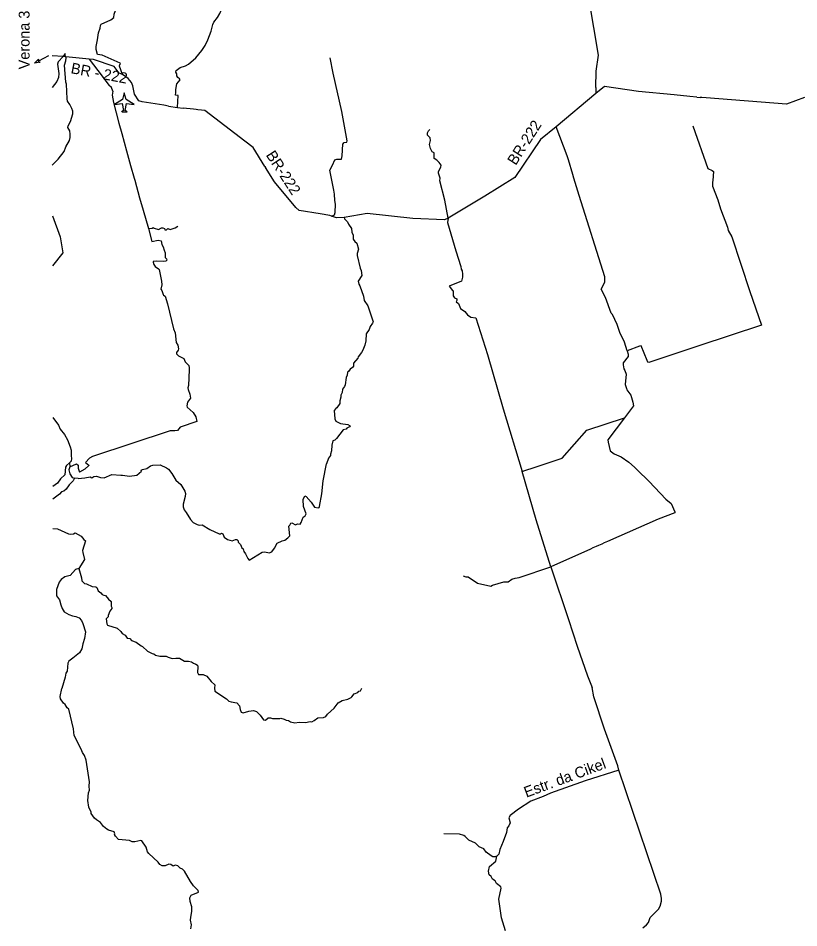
# Model space of a CAD drawing. Extents: x 332 to 501, y 9447 to 9559.
# Drawn here: x 332.35 to 359.78, y 9494.03 to 9526 of the extents above; entities that cross this region are included whole.
import ezdxf

# ---------------------------------------------------------------- set-up
doc = ezdxf.new("R2010")
doc.units = 0
for name, color, linetype in [('Level 1', 7, 'Continuous'), ('Level 12', 7, 'Continuous'), ('Level 2', 7, 'Continuous'), ('Level 31', 7, 'Continuous'), ('Level 4', 7, 'Continuous'), ('Level 5', 7, 'Continuous'), ('Level 6', 7, 'Continuous'), ('Level 8', 7, 'Continuous')]:
    doc.layers.add(name, color=color, linetype=linetype)

msp = doc.modelspace()

# ---------------------------------------------------------------- linework, layer by layer
at = {"layer": 'Level 1'}
for p, q in [((336.0741, 9523.3737), (336.0091, 9523.1363)), ((336.1441, 9523.1387), (336.0741, 9523.3737)), ((336.0091, 9523.1363), (335.7266, 9522.9563)), ((335.7266, 9522.9563), (336.0016, 9523.0013)), ((336.0016, 9523.0013), (336.0491, 9522.7487)), ((336.1066, 9522.7487), (336.1516, 9523.0013)), ((336.4266, 9522.9563), (336.1441, 9523.1387)), ((336.1516, 9523.0013), (336.4266, 9522.9563)), ((336.0491, 9522.7487), (335.9791, 9522.7037)), ((336.0016, 9522.7037), (336.1516, 9522.7037)), ((336.1741, 9522.7037), (336.1066, 9522.7487)), ((336.1516, 9522.7037), (336.1741, 9522.7037))]:
    msp.add_line(p, q, dxfattribs=at)
at = {"layer": 'Level 12'}
msp.add_line((333.4081, 9524.6683), (333.055, 9524.4804), dxfattribs=at)
msp.add_lwpolyline([(333.0652, 9524.5527), (333.0553, 9524.5395), (333.0502, 9524.5277), (333.0476, 9524.5093), (333.0517, 9524.4866), (333.055, 9524.4804), (333.0643, 9524.4672), (333.0753, 9524.4572), (333.0889, 9524.4509), (333.1041, 9524.4477), (333.1207, 9524.4485), (332.9217, 9524.4095)], close=True, dxfattribs=at)
at = {"layer": 'Level 2'}
for points in [[(333.9235, 9524.6472), (333.535, 9524.6698)], [(334.0181, 9524.6391), (333.9235, 9524.6472)], [(334.8453, 9524.5576), (334.0181, 9524.6391)], [(335.7215, 9524.2976), (334.991, 9524.5432), (334.8453, 9524.5576)], [(336.0143, 9524.0187), (335.897, 9524.066), (335.7215, 9524.2976)], [(337.4688, 9522.9428), (336.7, 9523.054), (336.587, 9523.092), (336.428, 9523.324), (336.37, 9523.616), (336.324, 9523.735), (336.207, 9523.873), (336.0143, 9524.0187)], [(355.3959, 9523.2977), (354.1443, 9523.4167), (352.9539, 9523.5929), (352.6494, 9523.3443)], [(352.6494, 9523.3443), (351.2461, 9522.1806)], [(355.9458, 9523.2454), (355.3959, 9523.2977)], [(356.1976, 9523.2249), (355.9458, 9523.2454)], [(337.631, 9522.9075), (337.4688, 9522.9428)], [(356.1976, 9523.2249), (356.3094, 9523.2108)], [(356.3767, 9523.2044), (356.3094, 9523.2108)], [(356.5186, 9523.1911), (356.3767, 9523.2044)], [(359.9733, 9523.2053), (359.3502, 9522.9681), (356.5186, 9523.1911)], [(337.631, 9522.9075), (337.939, 9522.8614)], [(337.939, 9522.8614), (338.1482, 9522.8301)], [(338.5034, 9522.795), (338.1482, 9522.8301)], [(338.6059, 9522.7819), (338.5034, 9522.795)], [(338.6545, 9522.7758), (338.6059, 9522.7819)], [(338.7834, 9522.7652), (338.6545, 9522.7758)], [(338.9037, 9522.7565), (338.7834, 9522.7652)], [(340.3057, 9521.6762), (338.9037, 9522.7565)], [(351.2461, 9522.1806), (350.7068, 9521.7347), (349.7974, 9520.4022), (348.7487, 9519.7374), (347.4519, 9518.9685)], [(341.0112, 9520.7828), (340.5986, 9521.4515), (340.3057, 9521.6762)], [(341.0112, 9520.7828), (341.0313, 9520.7476)], [(341.3576, 9520.2458), (341.0313, 9520.7476)], [(342.959, 9519.1147), (342.2235, 9519.2394), (342.1022, 9519.342), (341.3576, 9520.2458)], [(343.3553, 9519.0321), (343.302, 9519.0566), (342.959, 9519.1147)], [(347.4519, 9518.9685), (347.3239, 9518.9044), (346.2112, 9518.9605), (344.6068, 9519.1287), (343.805, 9518.995)], [(343.805, 9518.995), (343.5341, 9518.9845), (343.3553, 9519.0321)]]:
    msp.add_lwpolyline(points, dxfattribs=at)
at = {"layer": 'Level 4'}
for points in [[(339.2202, 9525.8532), (339.3509, 9526.0211), (339.4284, 9526.1549), (339.4636, 9526.2465), (339.4777, 9526.4155), (339.5693, 9526.648), (339.7876, 9527.0706), (339.999, 9527.4228), (340.0483, 9527.5848), (339.9708, 9528.5005), (340.2173, 9528.74), (340.2737, 9528.7612), (340.3165, 9528.8076)], [(352.6514, 9523.5639), (352.6517, 9524.1375), (352.7345, 9524.693), (352.2393, 9527.6988)], [(335.909, 9524.309), (335.913, 9524.367), (335.938, 9524.393), (335.929, 9524.417), (335.292, 9524.697), (335.13, 9524.716), (335.084, 9524.893), (335.083, 9524.998), (335.139, 9525.23), (335.167, 9525.477), (335.222, 9525.649), (335.233, 9525.738), (335.262, 9525.787), (335.6, 9525.941), (335.708, 9526.015), (335.724, 9526.14), (335.764, 9526.266), (336.093, 9526.829)], [(337.8911, 9523.4836), (337.917, 9523.685), (338.035, 9523.823), (338.017, 9523.869), (337.955, 9523.915), (337.922, 9523.969), (337.917, 9524.043), (337.881, 9524.094), (337.896, 9524.162), (338.039, 9524.261), (338.228, 9524.326), (338.334, 9524.38), (338.585, 9524.607), (338.801, 9524.856), (338.917, 9525.032), (339.014, 9525.229), (339.128, 9525.534), (339.186, 9525.777), (339.2202, 9525.8532)], [(336.0143, 9524.0187), (335.909, 9524.309)], [(352.6514, 9523.5639), (352.6494, 9523.3443)], [(337.8816, 9523.3829), (337.8851, 9523.4365)], [(337.8851, 9523.4365), (337.8911, 9523.4836)], [(347.4519, 9518.9685), (347.4283, 9518.8161), (347.7248, 9517.8154), (347.9027, 9517.2743), (347.9155, 9517.1802)], [(347.9155, 9517.1802), (347.9446, 9517.1219), (347.9636, 9517.0028)], [(347.9636, 9517.0028), (347.963, 9516.896), (347.9297, 9516.7564), (347.4941, 9516.5735), (347.6139, 9516.4274)], [(347.6139, 9516.4274), (347.6284, 9516.4108), (347.6284, 9516.2402), (347.6803, 9516.1734), (347.7619, 9516.1289), (347.7619, 9516.077), (347.7396, 9516.0251), (347.8212, 9515.9658), (347.8953, 9515.7952), (348.0435, 9515.6913), (348.1399, 9515.5726), (348.2585, 9515.4836), (348.429, 9515.4614), (348.8441, 9514.1729), (349.3927, 9512.2696), (350.0534, 9510.0646)], [(351.0641, 9506.7186), (350.5463, 9508.3639), (350.0534, 9510.0646)], [(351.0641, 9506.7186), (351.6898, 9504.8611), (351.9871, 9503.9312), (352.35, 9502.8786), (352.5189, 9502.4702)], [(353.453, 9499.569), (353.418, 9499.717), (352.949, 9501.009), (352.571, 9502.149), (352.5189, 9502.4702)], [(353.453, 9499.569), (352.272, 9499.196), (351.049, 9498.765), (350.8, 9498.641), (350.367, 9498.48), (349.928, 9498.197), (349.64, 9497.981), (349.592, 9497.889), (349.632, 9497.712), (349.585, 9497.609), (349.529, 9497.547), (349.503, 9497.383), (349.391, 9497.059), (349.272, 9496.786), (349.24, 9496.612), (349.163, 9496.549)]]:
    msp.add_lwpolyline(points, dxfattribs=at)
at = {"layer": 'Level 5'}
for points in [[(333.9235, 9524.6472), (333.7523, 9524.4593), (333.7328, 9524.3744), (333.7719, 9524.0548), (333.7654, 9523.9112), (333.7067, 9523.7742), (333.5372, 9523.5608)], [(333.5426, 9520.8298), (333.751, 9521.036), (333.967, 9521.311), (334.023, 9521.477), (334.154, 9521.697), (334.17, 9521.804), (334.178, 9521.921), (334.165, 9522.032), (334.085, 9522.152), (334.099, 9522.216), (334.18, 9522.37), (334.264, 9522.634), (334.261, 9522.724), (334.233, 9522.824), (334.165, 9522.967), (334.083, 9523.076), (334.065, 9523.166), (334.039, 9523.676), (334.019, 9523.742), (333.971, 9524.34), (334.016, 9524.495), (334.031, 9524.603), (334.0181, 9524.6391)], [(334.002, 9524.75), (333.9235, 9524.6472)], [(334.0181, 9524.6391), (334.001, 9524.687), (334.002, 9524.75)], [(334.8453, 9524.5576), (335.1499, 9524.1544)], [(343.4354, 9519.9492), (343.2997, 9520.6532), (343.3958, 9520.8307), (343.4698, 9521.0157), (343.5438, 9521.0379), (343.7066, 9521.0453), (343.7288, 9521.1637), (343.751, 9521.5706), (343.8028, 9521.6224), (343.8989, 9521.6372), (343.9063, 9521.6816), (343.714, 9522.7174), (343.4106, 9524.0636), (343.3066, 9524.6025)], [(335.1499, 9524.1544), (335.5455, 9523.6255)], [(335.6673, 9523.4364), (335.6199, 9523.5583), (335.5455, 9523.6255)], [(335.6673, 9523.4364), (335.648, 9523.288), (335.696, 9523.031), (335.885, 9522.301)], [(335.885, 9522.301), (335.9847, 9521.9435)], [(347.138, 9520.9247), (347.0586, 9521.0036), (346.9649, 9521.0661), (346.9649, 9521.2615), (346.8946, 9521.3006), (346.8399, 9521.41), (346.8009, 9521.5507), (346.8399, 9521.6914), (346.824, 9521.7937), (346.7333, 9521.8821), (346.7333, 9521.9657), (346.7595, 9522.0373), (346.8121, 9522.0874)], [(351.638, 9521.1598), (351.2461, 9522.1806)], [(356.0594, 9522.2118), (356.5866, 9520.7099), (356.7326, 9520.6481), (356.7775, 9520.6043), (356.7606, 9520.2898), (356.7438, 9520.228), (356.7494, 9520.0932), (356.9346, 9519.617), (357.0244, 9519.2912), (357.277, 9518.6471), (357.2995, 9518.5292), (357.4286, 9518.3101), (358.0531, 9516.3915)], [(335.9847, 9521.9435), (336.1568, 9521.3369)], [(336.1568, 9521.3369), (336.298, 9520.813)], [(351.6857, 9521.013), (351.638, 9521.1598)], [(351.8387, 9520.5037), (351.6857, 9521.013)], [(336.298, 9520.813), (336.418, 9520.371)], [(347.4519, 9518.9685), (347.335, 9519.5949), (347.1688, 9520.2782), (347.1749, 9520.3706), (347.1195, 9520.5491), (347.1134, 9520.6107), (347.1934, 9520.7646), (347.2057, 9520.8262), (347.138, 9520.9247)], [(336.418, 9520.371), (336.445, 9520.297)], [(351.8765, 9520.378), (351.8387, 9520.5037)], [(352.0644, 9519.7646), (351.8765, 9520.378)], [(336.445, 9520.297), (336.608, 9519.6853)], [(343.3553, 9519.0321), (343.4648, 9519.0831), (343.4862, 9519.166), (343.4942, 9519.4573), (343.4701, 9519.5937), (343.4674, 9519.8102), (343.4354, 9519.9492)], [(353.2269, 9515.5762), (353.1844, 9515.6328), (352.9866, 9516.18), (352.8379, 9516.4774), (352.9582, 9516.7182), (352.9653, 9516.9024), (352.0644, 9519.7646)], [(333.5461, 9519.0458), (333.8218, 9518.3117), (333.9142, 9517.747), (333.5496, 9517.2891)], [(343.805, 9518.995), (343.812, 9518.9464), (343.9164, 9518.842), (343.9499, 9518.7563), (344.0618, 9518.6071), (344.0767, 9518.4803), (344.1177, 9518.3685), (344.1214, 9518.2268), (344.1737, 9518.1485), (344.252, 9518.0888), (344.3042, 9517.8837), (344.2631, 9517.7308), (344.2631, 9517.6525), (344.3638, 9517.2063), (344.3974, 9517.128), (344.4235, 9516.9526), (344.293, 9516.7526), (344.3153, 9516.6481), (344.3489, 9516.5884), (344.4757, 9516.2265), (344.5055, 9516.0735), (344.6323, 9515.8847), (344.815, 9515.3288), (344.7964, 9515.2765), (344.7181, 9515.1609), (344.6845, 9515.0601), (344.5764, 9514.9072), (344.5652, 9514.6515), (344.5279, 9514.5098), (344.4533, 9514.3232), (344.416, 9514.2523), (344.293, 9514.0993), (344.2855, 9514.0508), (344.1326, 9513.8717), (344.1326, 9513.7673), (344.0991, 9513.7225), (344.0133, 9513.6568), (343.9574, 9513.5822), (343.9164, 9513.5598), (343.9089, 9513.4553), (343.8753, 9513.3732), (343.8418, 9513.1083), (343.8157, 9513.0524), (343.7411, 9512.9628), (343.7299, 9512.8374), (343.6814, 9512.7441)], [(358.0531, 9516.3915), (358.4654, 9515.2101)], [(353.7436, 9514.3013), (353.6516, 9514.6059), (353.4888, 9514.9458), (353.3897, 9515.2291), (353.2269, 9515.5762)], [(358.4654, 9515.2101), (356.2602, 9514.4786)], [(353.7436, 9514.3013), (353.7822, 9514.1852), (353.7861, 9514.1061), (353.6082, 9513.8808), (353.6043, 9513.8176), (353.628, 9513.6674), (353.6636, 9513.612), (353.7071, 9513.4895), (353.6715, 9513.1219), (353.7268, 9512.9852), (353.7308, 9512.9338), (353.8731, 9512.7479), (353.9482, 9512.5027), (353.9679, 9512.3722), (353.6537, 9511.9499)], [(356.0149, 9514.3955), (354.508, 9513.8976), (354.4726, 9513.9047), (354.4443, 9513.9614), (354.239, 9514.4784), (354.1824, 9514.4713), (353.7436, 9514.3013)], [(356.13, 9514.4345), (356.0149, 9514.3955)], [(356.2602, 9514.4786), (356.13, 9514.4345)], [(343.6814, 9512.7441), (343.6889, 9512.6732), (343.6479, 9512.5464), (343.6516, 9512.4494), (343.5435, 9512.3001), (343.5062, 9512.2778), (343.4503, 9512.2031), (343.4764, 9511.9158), (343.5062, 9511.8375), (343.6777, 9511.7569), (343.9313, 9511.7196), (344.0096, 9511.6636), (343.9909, 9511.63), (343.8977, 9511.589), (343.8679, 9511.5554), (343.7709, 9511.5293), (343.536, 9511.2196), (343.4764, 9511.1636), (343.4018, 9511.145), (343.3645, 9510.9942), (343.3608, 9510.7927), (343.3197, 9510.6696), (343.3197, 9510.6248), (343.2564, 9510.5278), (343.186, 9510.337)], [(333.5603, 9511.9633), (333.7603, 9511.6975), (333.8181, 9511.5529), (333.9722, 9511.3698), (334.0782, 9511.1771), (334.1745, 9510.9265), (334.2034, 9510.8108), (334.2034, 9510.618), (334.2227, 9510.5216), (334.2034, 9510.4253), (334.146, 9510.3714)], [(350.3736, 9510.1693), (351.4645, 9510.5353), (352.3296, 9511.5169), (353.6537, 9511.9499)], [(353.6537, 9511.9499), (353.0707, 9511.177), (353.0746, 9511.094), (353.1497, 9510.7894), (353.292, 9510.6906), (353.5371, 9510.5838), (353.8019, 9510.3979), (353.9993, 9510.2148)], [(334.146, 9510.3714), (334.0493, 9510.2807), (334.0108, 9510.2132), (333.9819, 9509.953), (333.8374, 9509.8084), (333.7314, 9509.6542), (333.5652, 9509.5365)], [(334.1649, 9510.2228), (334.1309, 9510.1217), (334.1566, 9509.9781), (334.2464, 9509.8575), (334.3212, 9509.8258)], [(334.146, 9510.3714), (334.1649, 9510.2228)], [(334.1649, 9510.2228), (334.3961, 9510.3289), (334.4539, 9510.2903), (334.4539, 9510.1843), (334.498, 9510.04)], [(334.692, 9510.15), (334.498, 9510.04)], [(334.8289, 9510.2779), (334.692, 9510.15)], [(334.8299, 9510.2791), (334.8289, 9510.2779)], [(335.95, 9509.93), (336.009, 9509.941), (336.258, 9509.899), (336.515, 9509.936), (336.683, 9510.081), (336.672, 9510.116), (336.713, 9510.138), (336.865, 9510.169), (336.99, 9510.269), (337.081, 9510.287), (337.337, 9510.294), (337.56, 9510.198), (337.624, 9510.147), (337.749, 9509.992), (337.8899, 9509.7634), (338.062, 9509.611), (338.207, 9509.379), (338.221, 9509.297), (338.215, 9509.186), (338.141, 9508.912), (338.139, 9508.819), (338.175, 9508.712), (338.247, 9508.624), (338.405, 9508.372), (338.497, 9508.274), (338.63, 9508.2), (338.701, 9508.183), (338.807, 9508.192), (339.082, 9508.027), (339.411, 9507.877), (339.451, 9507.873), (339.486, 9507.895), (339.535, 9507.875), (339.586, 9507.761), (339.696, 9507.679)], [(343.013, 9509.277), (343.066, 9509.742), (343.186, 9510.337)], [(350.1461, 9510.0949), (350.2577, 9510.1314)], [(350.2577, 9510.1314), (350.3736, 9510.1693)], [(353.9993, 9510.2148), (354.0982, 9510.1227)], [(334.4534, 9509.8131), (334.3212, 9509.8258)], [(334.4534, 9509.8131), (334.6914, 9509.8371), (334.8731, 9509.8775), (334.9387, 9509.8472), (335.0043, 9509.8876), (335.0951, 9509.9027), (335.2364, 9509.8573), (335.3726, 9509.8422), (335.64, 9509.9532), (335.95, 9509.93)], [(350.0534, 9510.0646), (350.0566, 9510.0656)], [(350.0566, 9510.0656), (350.1461, 9510.0949)], [(354.0982, 9510.1227), (354.5213, 9509.7109), (355.1096, 9509.0872), (355.2874, 9508.9425), (355.4258, 9508.6419), (355.4179, 9508.6142), (354.8368, 9508.3848), (353.0576, 9507.6027)], [(339.696, 9507.679), (339.868, 9507.627), (339.982, 9507.673), (340.033, 9507.673), (340.072, 9507.632), (340.079, 9507.583), (340.158, 9507.498), (340.211, 9507.378), (340.248, 9507.349), (340.277, 9507.25), (340.339, 9507.17), (340.414, 9507.004), (340.468, 9506.943), (340.921, 9507.231), (341.012, 9507.239), (341.168, 9507.208), (341.256, 9507.244), (341.352, 9507.373), (341.443, 9507.546), (341.625, 9507.628), (341.714, 9507.651), (341.824, 9507.733), (341.893, 9507.809), (341.853, 9508.147), (341.898, 9508.179), (341.925, 9508.249), (341.963, 9508.26), (342.092, 9508.187), (342.166, 9508.227), (342.25, 9508.216), (342.293, 9508.274), (342.365, 9508.463), (342.435, 9508.501), (342.462, 9508.571), (342.376, 9508.837), (342.357, 9509.08), (342.418, 9509.207), (342.461, 9509.183), (342.644, 9508.986), (342.764, 9508.816), (342.89, 9508.782), (342.926, 9508.797), (342.94, 9508.834), (343.013, 9509.277)], [(353.0576, 9507.6027), (352.9424, 9507.5521)], [(352.4616, 9507.3408), (351.0641, 9506.7186)], [(352.5441, 9507.3771), (352.4616, 9507.3408)], [(352.6583, 9507.4273), (352.5441, 9507.3771)], [(352.7449, 9507.4653), (352.6583, 9507.4273)], [(352.8518, 9507.5123), (352.7449, 9507.4653)], [(352.9424, 9507.5521), (352.8518, 9507.5123)], [(347.9843, 9506.4026), (348.0737, 9506.3579), (348.1556, 9506.3579), (348.4907, 9506.1419), (348.9524, 9506.0302), (349.012, 9506.0675), (349.4141, 9506.1866), (349.5705, 9506.1866), (349.6971, 9506.2834), (349.8162, 9506.3207), (349.9503, 9506.3356), (351.0641, 9506.7186)], [(354.302, 9494.027), (354.421, 9494.128), (354.494, 9494.213), (354.551, 9494.39), (354.851, 9494.682), (354.909, 9494.788), (354.949, 9494.969), (354.953, 9495.062), (354.925, 9495.208), (353.453, 9499.569)], [(338.189, 9496.016), (338.124, 9496.088), (338.044, 9496.129), (337.958, 9496.207), (337.864, 9496.224), (337.787, 9496.194), (337.709, 9496.252), (337.645, 9496.259), (337.512, 9496.201), (337.41, 9496.208), (337.327, 9496.258), (337.268, 9496.336), (336.932, 9496.643), (336.894, 9496.704), (336.844, 9496.858), (336.688, 9497.084), (336.658, 9497.098), (336.451, 9497.047), (336.354, 9497.05), (336.255, 9497.102), (335.877, 9497.133), (335.765, 9497.247), (335.731, 9497.303), (335.746, 9497.327), (335.723, 9497.407), (335.52, 9497.465), (335.46, 9497.5), (335.347, 9497.593), (335.242, 9497.725), (335.0957, 9497.8209)], [(349.163, 9496.549), (349.0932, 9496.5193), (349.025, 9496.5233), (348.9689, 9496.5554), (348.7966, 9496.6917), (348.7084, 9496.7999), (348.548, 9496.872), (348.4118, 9497.0043), (348.4118, 9497.0043), (348.1793, 9497.1125), (348.051, 9497.2368), (348.0069, 9497.2729), (347.8506, 9497.317), (347.3095, 9497.329)], [(349.4673, 9493.9227), (349.3353, 9494.3822), (349.2347, 9495.0328), (349.3227, 9495.423), (349.3038, 9495.4671), (349.1529, 9495.5867), (349.1026, 9495.6748), (349.0146, 9495.7378), (348.9643, 9495.8322), (348.8951, 9495.8888), (348.8762, 9496.021), (348.914, 9496.1784), (349.1278, 9496.3672), (349.163, 9496.549)], [(338.417, 9493.997), (338.436, 9494.128), (338.407, 9494.296), (338.41, 9494.408), (338.448, 9494.599), (338.451, 9494.768), (338.387, 9494.952), (338.376, 9495.083), (338.424, 9495.172), (338.678, 9495.281), (338.676, 9495.339), (338.506, 9495.509), (338.402, 9495.65), (338.189, 9496.016)]]:
    msp.add_lwpolyline(points, dxfattribs=at)
at = {"layer": 'Level 6'}
for points in [[(336.608, 9519.6853), (336.742, 9519.244)], [(336.742, 9519.244), (336.9197, 9518.6003)], [(336.9197, 9518.6003), (337.052, 9518.62), (337.094, 9518.643), (337.119, 9518.613), (337.276, 9518.569), (337.38, 9518.626), (337.43, 9518.629), (337.482, 9518.608), (337.5, 9518.56), (337.553, 9518.563), (337.609, 9518.599), (337.692, 9518.57), (337.861, 9518.626), (337.958, 9518.683)], [(336.9197, 9518.6003), (337.042, 9518.149)], [(337.042, 9518.149), (337.261, 9518.195), (337.371, 9518.174), (337.395, 9518.047), (337.443, 9517.957), (337.473, 9517.837), (337.514, 9517.748), (337.514, 9517.585), (337.556, 9517.543), (337.569, 9517.494), (337.537, 9517.456), (337.455, 9517.439), (337.211, 9517.461), (337.093, 9517.445), (337.089, 9517.423), (337.115, 9517.334), (337.156, 9517.264), (337.277, 9517.187), (337.295, 9517.159), (337.385, 9516.751), (337.393, 9516.63), (337.354, 9516.467), (337.398, 9516.42), (337.446, 9516.285)], [(337.446, 9516.285), (337.455, 9516.26), (337.508, 9516.223), (337.59, 9515.962), (337.801, 9515.073), (337.859, 9514.933), (337.8981, 9514.5927)], [(337.8981, 9514.5927), (337.951, 9514.509), (337.982, 9514.371), (337.972, 9514.332), (337.906, 9514.241), (337.908, 9514.201), (337.985, 9514.128), (338.164, 9514.034), (338.213, 9513.92), (338.338, 9513.792), (338.359, 9513.708), (338.358, 9513.636), (338.328, 9513.091), (338.31, 9513.004), (338.317, 9512.942), (338.382, 9512.781), (338.397, 9512.637)], [(338.397, 9512.637), (338.294, 9512.503), (338.272, 9512.377), (338.288, 9512.32), (338.496, 9512.134), (338.5839, 9511.9872)], [(338.6276, 9511.8271), (338.04, 9511.62), (337.939, 9511.503), (337.847, 9511.489), (337.691, 9511.499), (334.957, 9510.595), (334.851, 9510.535), (334.713, 9510.379)], [(338.5839, 9511.9872), (338.6276, 9511.8271)], [(334.713, 9510.379), (334.8251, 9510.2836)], [(334.8251, 9510.2836), (334.8252, 9510.2836)], [(334.8252, 9510.2836), (334.8283, 9510.2806)], [(334.8283, 9510.2806), (334.8299, 9510.2791)], [(334.3212, 9509.8258), (334.2827, 9509.7312)], [(334.2827, 9509.7312), (334.1359, 9509.5967), (334.035, 9509.4402), (333.9542, 9509.3746), (333.8685, 9509.3443), (333.7928, 9509.2635), (333.5661, 9509.0865)], [(333.5682, 9508.066), (333.7221, 9508.0467), (334.1107, 9507.8751), (334.1864, 9507.8599), (334.2873, 9507.87), (334.3529, 9507.9104), (334.5597, 9507.7943), (334.6506, 9507.6731), (334.7162, 9507.6226), (334.6102, 9507.2922), (334.6153, 9507.2165), (334.6758, 9506.9741), (334.479, 9506.6611)], [(334.479, 9506.6611), (334.363, 9506.6156), (334.1763, 9506.4086), (333.9845, 9506.3683), (333.8584, 9506.2723), (333.7877, 9506.1764), (333.6868, 9505.9189), (333.6868, 9505.6967), (333.8029, 9505.5568), (333.8432, 9505.3751), (333.8937, 9505.2489), (333.9643, 9505.1327), (334.1258, 9505.0368), (334.2519, 9504.9863), (334.368, 9504.9712), (334.4841, 9504.9207), (334.5698, 9504.8247), (334.6153, 9504.7257), (334.7061, 9504.4278), (334.6808, 9504.1956), (334.6153, 9504.0037), (334.5799, 9503.8321), (334.4992, 9503.6972), (334.2721, 9503.5003), (334.1258, 9503.4044), (334.0905, 9503.3236), (334.0703, 9503.0509), (334.0198, 9502.9752), (333.9946, 9502.8338), (333.8782, 9502.4341)], [(334.479, 9506.6611), (334.5698, 9506.3295), (334.5799, 9506.2235), (334.6253, 9506.173), (334.6808, 9506.1326), (334.7515, 9506.1225), (334.9483, 9506.0215), (335.0744, 9506.0064), (335.1047, 9505.9862), (335.1552, 9505.865), (335.251, 9505.8044), (335.2914, 9505.7438), (335.3519, 9505.7135), (335.4175, 9505.7034), (335.5185, 9505.5772), (335.6143, 9505.4964), (335.6143, 9505.3298), (335.6396, 9505.2894), (335.6345, 9505.249), (335.5639, 9505.1582), (335.5084, 9505.0067), (335.5084, 9504.9562), (335.4327, 9504.8855), (335.4579, 9504.7088), (335.4831, 9504.6634), (335.8198, 9504.5598), (335.9561, 9504.4386), (336.0015, 9504.373), (336.1074, 9504.3073), (336.1781, 9504.2063), (336.2639, 9504.1963), (336.3295, 9504.1205), (336.4909, 9504.065), (336.6675, 9503.9337), (336.7129, 9503.9186), (336.8845, 9503.7519), (337.051, 9503.6712), (337.1166, 9503.656), (337.1721, 9503.6156), (337.3184, 9503.5702), (337.5455, 9503.5803), (337.6161, 9503.5399), (337.7625, 9503.4945), (337.8836, 9503.5096), (338.0097, 9503.5046), (338.1964, 9503.4036), (338.2671, 9503.3935), (338.3276, 9503.4036), (338.4423, 9503.3697), (338.5028, 9503.3242), (338.5886, 9503.294), (338.6441, 9503.2536), (338.6643, 9503.2031), (338.6441, 9503.0011), (338.6845, 9502.9355), (338.8409, 9502.9254), (338.9721, 9502.8749), (339.1285, 9502.6881), (339.2547, 9502.5669), (339.2456, 9502.445)], [(344.068, 9502.147), (344.1588, 9502.2484), (344.2795, 9502.2954), (344.3198, 9502.3389), (344.37, 9502.3557), (344.418, 9502.4551)], [(335.0957, 9497.8209), (335.026, 9497.887), (334.913, 9498.04), (334.908, 9498.088), (334.834, 9498.265), (334.799, 9498.499), (334.822, 9498.776), (334.856, 9498.863), (334.842, 9499.005), (334.853, 9499.155), (334.739, 9499.916), (334.672, 9500.089), (334.605, 9500.195), (334.565, 9500.302), (334.317, 9500.781), (334.287, 9501.019), (334.122, 9501.714), (334.062, 9501.764), (333.997, 9501.878), (333.939, 9501.919), (333.836, 9502.076), (333.816, 9502.162), (333.8782, 9502.4341)], [(339.2456, 9502.445), (339.252, 9502.341), (339.668, 9502.078), (339.754, 9501.998), (339.828, 9501.97), (340.0335, 9501.9375), (340.1248, 9501.8245), (340.1415, 9501.7009), (340.1816, 9501.6008), (340.2484, 9501.5841), (340.448, 9501.639), (340.621, 9501.66), (340.716, 9501.63), (340.7459, 9501.6041)], [(340.7459, 9501.6041), (340.844, 9501.503), (340.961, 9501.34), (341.037, 9501.33), (341.125, 9501.406), (341.2117, 9501.4071), (341.2885, 9501.387), (341.544, 9501.387), (341.574, 9501.399), (341.696, 9501.364), (341.767, 9501.323), (341.847, 9501.314), (341.912, 9501.267), (342.0698, 9501.2368), (342.2253, 9501.2545), (342.448, 9501.245), (342.61, 9501.278), (342.663, 9501.271), (342.749, 9501.312), (342.874, 9501.41), (343.071, 9501.423), (343.156, 9501.46), (343.214, 9501.54), (343.445, 9501.753), (343.588, 9501.934), (343.731, 9502.022), (343.934, 9502.062), (344.046, 9502.117), (344.068, 9502.147)]]:
    msp.add_lwpolyline(points, dxfattribs=at)
at = {"layer": 'Level 8'}
msp.add_lwpolyline([(337.939, 9522.8614), (337.972, 9523.275), (337.876, 9523.294), (337.8816, 9523.3829)], dxfattribs=at)

# ---------------------------------------------------------------- texts
at = {"layer": 'Level 12'}
msp.add_text('Verona 3,3 km', height=0.38, rotation=90, dxfattribs=at).set_placement((332.7464, 9524.1976))
at = {"layer": 'Level 31'}
for s, rotation, p in [('BR - 222', 349.29453, (334.1747, 9524.0646)), ('BR-222', 57.37543, (349.8293, 9520.8002)), ('BR-222', 303.09219, (341.038, 9521.1869)), ('Estr. da Cikel', 20.33624, (350.2043, 9498.5994))]:
    msp.add_text(s, height=0.38, rotation=rotation, dxfattribs=at).set_placement(p)

doc.saveas('drawing.dxf')
